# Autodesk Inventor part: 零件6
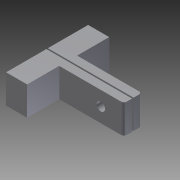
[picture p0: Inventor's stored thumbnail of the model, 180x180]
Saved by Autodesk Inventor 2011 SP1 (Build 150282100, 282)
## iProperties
Created: 2014-02
Part Number: 零件6
Document SubType Name: Modeling
Designer: yn
Density: 1 g/cm^3
Author: yn
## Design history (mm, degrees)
sketch "草图1"
  geometry: L1 (0, 0)-(0, 14.234); L2 (0, 14.234)-(7.299, 14.234); L3 (7.299, 14.234)-(7.299, 3.102); L4 (7.299, 3.102)-(29.745, 3.102); L5 (29.745, 3.102)-(29.745, 0); L6 (29.745, 0)-(0, 0); L7 (0, 0)-(0, -14.234); L8 (0, -14.234)-(7.299, -14.234); L9 (7.299, -14.234)-(7.299, -3.102); L10 (7.299, -3.102)-(29.745, -3.102); L11 (29.745, -3.102)-(29.745, 0)
  constraints: 22 end point, 4 parallel, 4 symmetric about line, 1 perpendicular, 1 vertical
extrude "拉伸1" new body sketch "草图1" distance "d0" = 10; taper "d1" = 0 deg
sketch "草图2"
  geometry: L1 (0, -14.234)-(0, 14.234) reference; L2 (29.745, 3.102)-(29.745, -3.102) reference; L3 (0, 0.25)-(29.745, 0.25); L4 (29.745, 0.25)-(29.745, -0.25); L5 (29.745, -0.25)-(0, -0.25); L6 (0, -0.25)-(0, 0.25); 3 further points
  constraints: 8 end point, 4 midpoint, 2 parallel, 1 horizontal, 1 perpendicular
  dimensions: "d2" = 0.5 distance of L3.start L5.end
extrude "拉伸2" cut sketch "草图2" distance "d3" = 10; taper "d4" = 0 deg
hole "Hole1" diameter "d7" = 1; stored, may be unused: countersink angle "d11" = 10 deg, drill point angle "d13" = 118 deg; dims "d5" = 5, "d6" = 8, "d8" = 6, "d9" = 4, "d10" = 2, "d12" = 8
fillet "圆角1" dims "d14" = 1
node "实体1"
